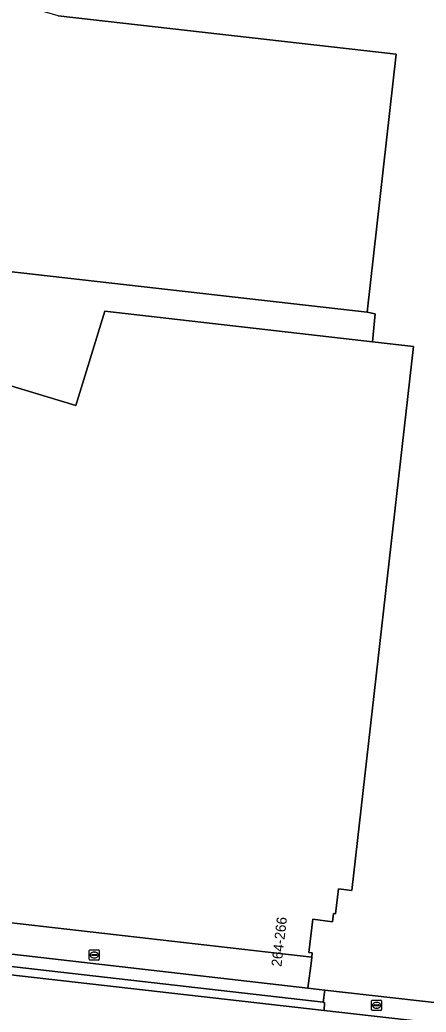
# Model space of a CAD drawing. Extents: x 161385 to 162589, y 388479 to 389756.
# Drawn here: x 162393.2 to 162433.2, y 388795 to 388892.6 of the extents above; entities that cross this region are included whole.
import ezdxf

# ---------------------------------------------------------------- set-up
doc = ezdxf.new("R2010")
doc.units = 0
for name, color, linetype in [('IMGEO_Berm_groen', 7, 'Continuous'), ('IMGEO_Brandkraan', 7, 'Continuous'), ('IMGEO_Erf', 7, 'Continuous'), ('IMGEO_Groenvoorziening', 7, 'Continuous'), ('IMGEO_Pand', 7, 'Continuous'), ('IMGEO_Pand_nummerreeks', 7, 'Continuous'), ('IMGEO_Rijbaan_lokaal_gesloten', 7, 'Continuous'), ('IMGEO_Rioolput', 7, 'Continuous'), ('IMGEO_Voetpad_open', 7, 'Continuous')]:
    doc.layers.add(name, color=color, linetype=linetype)

msp = doc.modelspace()

# ---------------------------------------------------------------- linework, layer by layer
at = {"layer": 'IMGEO_Berm_groen'}
msp.add_lwpolyline([(162382.567, 388800.591), (162382.484, 388799.768), (162423.146, 388795.15), (162423.198, 388795.915), (162423.063, 388795.942)], close=True, dxfattribs=at)
at = {"layer": 'IMGEO_Brandkraan'}
for p, q in [((162427.808, 388795.222), (162427.808, 388796.074)), ((162427.883, 388796.148), (162428.735, 388796.148)), ((162428.11, 388795.691), (162428.508, 388795.691)), ((162428.296, 388795.928), (162428.321, 388795.928)), ((162428.809, 388796.074), (162428.809, 388795.222)), ((162428.735, 388795.148), (162427.883, 388795.148)), ((162428.067, 388795.642), (162428.067, 388795.654)), ((162428.505, 388795.605), (162428.107, 388795.605)), ((162428.319, 388795.368), (162428.294, 388795.368)), ((162428.551, 388795.654), (162428.551, 388795.642))]:
    msp.add_line(p, q, dxfattribs=at)
for points in [[(162427.808, 388795.222), (162427.808, 388796.074)], [(162427.883, 388796.148), (162428.735, 388796.148)], [(162428.809, 388796.074), (162428.809, 388795.222)], [(162428.735, 388795.148), (162427.883, 388795.148)]]:
    msp.add_lwpolyline(points, dxfattribs=at)
for centre, radius, start, end in [((162427.885, 388796.072), 0.0765, 91.55205, 178.44795), ((162427.885, 388796.072), 0.0765, 91.55205, 178.44795), ((162428.107, 388795.651), 0.0403, 85.87752, 175.75265), ((162428.512, 388795.653), 0.0386, 1.73085, 96.63898), ((162428.733, 388796.072), 0.0765, 1.55205, 88.44795), ((162428.733, 388796.072), 0.0765, 1.55205, 88.44795), ((162427.885, 388795.224), 0.0765, 181.55205, 268.44795), ((162427.885, 388795.224), 0.0765, 181.55205, 268.44795), ((162428.104, 388795.641), 0.0366, 178.93798, 274.71019), ((162428.508, 388795.648), 0.043, 264.86636, 352.45326), ((162428.733, 388795.224), 0.0765, 271.55205, 358.44795), ((162428.733, 388795.224), 0.0765, 271.55205, 358.44795)]:
    msp.add_arc(centre, radius, start, end, dxfattribs=at)
for centre, major_axis, ratio, start_param, end_param in [((162428.295, 388795.648), (-0.387, 0.002), 0.722429, 4.712389, 7.853982), ((162428.32, 388795.648), (-0.39, 0.002), 0.717154, 1.570796, 4.712389)]:
    msp.add_ellipse(centre, major_axis=major_axis, ratio=ratio, start_param=start_param, end_param=end_param, dxfattribs=at)
at = {"layer": 'IMGEO_Erf'}
msp.add_lwpolyline([(162396.969, 388892.972), (162430.252, 388889.19), (162427.372, 388863.825), (162428.16, 388863.668), (162427.905, 388860.918), (162431.951, 388860.46), (162425.867, 388806.95), (162424.566, 388807.108), (162424.267, 388804.656), (162424.078, 388804.678), (162423.978, 388803.864), (162422.022, 388804.102), (162421.644, 388800.836), (162421.982, 388800.802), (162421.939, 388800.373), (162421.892, 388800.017), (162421.541, 388797.334), (162423.214, 388797.141), (162434.552, 388795.859)], dxfattribs=at)
at = {"layer": 'IMGEO_Groenvoorziening'}
for points in [[(162383.532, 388830.458), (162383.919, 388830.342), (162392.007, 388856.692), (162398.712, 388854.634), (162401.565, 388863.931), (162427.905, 388860.918), (162428.16, 388863.668), (162427.372, 388863.825), (162391.857, 388867.872), (162372.558, 388802.943), (162376.55, 388802.484), (162377.177, 388802.419), (162377.914, 388804.888), (162375.474, 388805.196), (162374.122, 388805.367), (162382.047, 388830.873)], [(162421.541, 388797.334), (162421.892, 388800.017), (162421.939, 388800.373), (162387.48, 388804.31), (162388.282, 388811.244), (162385.61, 388811.516), (162382.688, 388801.778)]]:
    msp.add_lwpolyline(points, close=True, dxfattribs=at)
at = {"layer": 'IMGEO_Pand'}
msp.add_lwpolyline([(162391.857, 388867.872), (162427.372, 388863.825), (162430.252, 388889.19), (162396.969, 388892.972), (162380.807, 388897.743), (162381.135, 388898.887), (162380.7, 388899.012), (162380.594, 388898.564), (162373.932, 388900.514), (162374.02, 388900.974), (162373.582, 388901.101), (162368.037, 388877.085), (162368.47, 388876.966), (162368.656, 388877.64), (162392.177, 388870.683)], close=True, dxfattribs=at)
msp.add_lwpolyline([(162387.48, 388804.31), (162421.939, 388800.373), (162421.982, 388800.802), (162421.644, 388800.836), (162422.022, 388804.102), (162423.978, 388803.864), (162424.078, 388804.678), (162424.267, 388804.656), (162424.566, 388807.108), (162425.867, 388806.95), (162431.951, 388860.46), (162427.905, 388860.918), (162401.565, 388863.931), (162398.712, 388854.634), (162392.007, 388856.692)], dxfattribs=at)
at = {"layer": 'IMGEO_Rijbaan_lokaal_gesloten'}
msp.add_lwpolyline([(162434.425, 388793.87), (162423.146, 388795.15), (162382.484, 388799.768)], dxfattribs=at)
at = {"layer": 'IMGEO_Rioolput'}
for p, q in [((162400.025, 388800.169), (162400.025, 388801.021)), ((162400.1, 388801.095), (162400.952, 388801.095)), ((162400.284, 388800.589), (162400.284, 388800.601)), ((162400.327, 388800.638), (162400.725, 388800.638)), ((162400.513, 388800.875), (162400.538, 388800.875)), ((162400.768, 388800.601), (162400.768, 388800.589)), ((162401.026, 388801.021), (162401.026, 388800.169)), ((162400.952, 388800.095), (162400.1, 388800.095)), ((162400.722, 388800.552), (162400.324, 388800.552)), ((162400.536, 388800.315), (162400.511, 388800.315))]:
    msp.add_line(p, q, dxfattribs=at)
for points in [[(162400.025, 388800.169), (162400.025, 388801.021)], [(162400.1, 388801.095), (162400.952, 388801.095)], [(162401.026, 388801.021), (162401.026, 388800.169)], [(162400.952, 388800.095), (162400.1, 388800.095)]]:
    msp.add_lwpolyline(points, dxfattribs=at)
for centre, radius, start, end in [((162400.102, 388801.019), 0.0765, 91.55205, 178.44795), ((162400.102, 388801.019), 0.0765, 91.55205, 178.44795), ((162400.324, 388800.598), 0.0403, 85.87752, 175.75265), ((162400.321, 388800.588), 0.0366, 178.93798, 274.71019), ((162400.725, 388800.595), 0.043, 264.86636, 352.45326), ((162400.729, 388800.6), 0.0386, 1.73085, 96.63898), ((162400.95, 388801.019), 0.0765, 1.55205, 88.44795), ((162400.95, 388801.019), 0.0765, 1.55205, 88.44795), ((162400.102, 388800.171), 0.0765, 181.55205, 268.44795), ((162400.102, 388800.171), 0.0765, 181.55205, 268.44795), ((162400.95, 388800.171), 0.0765, 271.55205, 358.44795), ((162400.95, 388800.171), 0.0765, 271.55205, 358.44795)]:
    msp.add_arc(centre, radius, start, end, dxfattribs=at)
for centre, major_axis, ratio, start_param, end_param in [((162400.512, 388800.595), (-0.387, 0.002), 0.722429, 4.712389, 7.853982), ((162400.537, 388800.595), (-0.39, 0.002), 0.717154, 1.570796, 4.712389)]:
    msp.add_ellipse(centre, major_axis=major_axis, ratio=ratio, start_param=start_param, end_param=end_param, dxfattribs=at)
at = {"layer": 'IMGEO_Voetpad_open'}
for points in [[(162421.541, 388797.334), (162382.688, 388801.778), (162382.567, 388800.591), (162423.063, 388795.942), (162423.214, 388797.141)], [(162434.65, 388795.848), (162434.552, 388795.859), (162423.214, 388797.141), (162423.063, 388795.942), (162423.198, 388795.915), (162423.146, 388795.15), (162434.425, 388793.87), (162434.513, 388794.642)]]:
    msp.add_lwpolyline(points, close=True, dxfattribs=at)

# ---------------------------------------------------------------- texts
at = {"layer": 'IMGEO_Pand_nummerreeks'}
msp.add_text('264-266', height=1, rotation=83.39808, dxfattribs=at).set_placement((162418.941, 388799.402))

doc.saveas('drawing.dxf')
